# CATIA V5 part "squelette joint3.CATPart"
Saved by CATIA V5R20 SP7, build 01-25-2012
Part number: squelette joint3
Publications: "Plan.1", "Plan.2", "Plan.3", "Point.1", "Droite.1", "Droite.2", "Point.2", "Droite.3", "antraxe", "longueur du pivoty", "epaisseur du pivoty", "rayon1 du pivotz", "rayon2 du pivotz", "demi_hauteur du pivotz", "rayon exterieur du lien", "rayon interieur du lien"
Bounding box of the stored display mesh (mm): x -145 to 0, y -40 to 0, z 0 to 40
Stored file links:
  D:\thinkmotion-MPB\Dropbox\Pack 1 sylvain\CFAO_2010_yyang\yyang\CFAO_2010_yyang\squelette joint3.CATPart
  D:\thinkmotion-MPB\Dropbox\Pack 1 sylvain\CFAO_2010_yyang\yyang\CFAO_2010_yyang\yyang.CATProduct
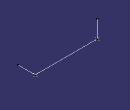
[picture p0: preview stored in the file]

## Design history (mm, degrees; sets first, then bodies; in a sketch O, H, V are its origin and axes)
Parameters
  antraxe = 145 mm {= `External.position horizontal du pivot1`+External.entraxe+`External.position horizontale du pivot2`}
  `longueur du pivoty` = 30 mm
  `epaisseur du pivoty` = 3 mm
  `rayon1 du pivotz` = 18 mm {= `External.rayon2 du tube`}
  `rayon2 du pivotz` = 21 mm
  `demi_hauteur du pivotz` = 25 mm
  `rayon exterieur du lien` = 18 mm
  `rayon interieur du lien` = 16 mm
External parameters (linked from other documents)
  `External.rayon2 du tube` = 18 mm
  `External.position horizontal du pivot1` = 45 mm
  External.entraxe = 50 mm
  `External.position horizontale du pivot2` = 50 mm
Body1 (main body)
  Plane1: type Offset, RefPlane xy-plane, Offset 0
  Plane2: type Offset, RefPlane yz-plane, Offset 0
  Plane3: type Offset, RefPlane zx-plane, Offset 0
  Point1: (0, 0, 0)
  Line1: type PtDir, RefPoint Point1, Direction (0, 1, 0), Start 0, End 40
  Line2: type PtDir, RefPoint Point1, Direction (1, 0, 0), Start 0, End 145 {= antraxe}
  Point2: (0, 0, 0), relative to vertex of Line2
  Line3: type PtDir, RefPoint Point2, Direction (0, 0, 1), Start 0, End 40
